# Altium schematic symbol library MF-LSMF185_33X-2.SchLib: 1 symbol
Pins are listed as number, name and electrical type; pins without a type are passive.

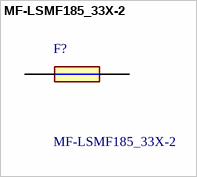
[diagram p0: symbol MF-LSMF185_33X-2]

## MF-LSMF185_33X-2
designator F?
PTC - (2920)SURFACE MNT Bourns 1.85A Surface Mount Resettable Fuse, 33 V; Manufacturer_Part_Number: MF-LSMF185/33X-2; Geometry.Height: 1.6mm
footprint FUSC7451X160N
pins: 1, 2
